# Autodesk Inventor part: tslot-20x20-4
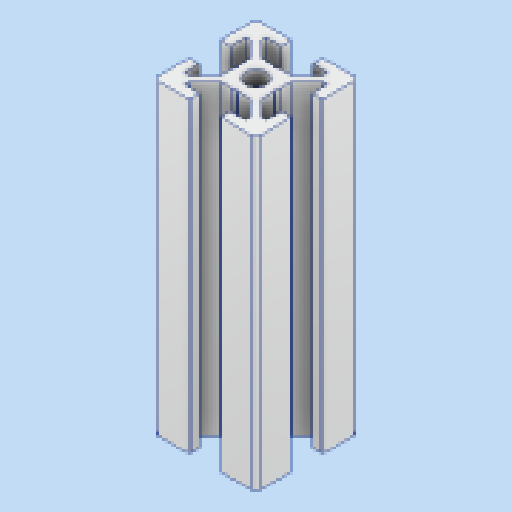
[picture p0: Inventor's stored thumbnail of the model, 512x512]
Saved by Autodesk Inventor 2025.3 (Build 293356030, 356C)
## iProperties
Created: 2025-03
Part Number: tslot-20x20-4
Material: Alluminio 6061
Document SubType Name: Modeling
Designer: Ryzen5700u
Density: 2.7 g/cm^3
Appearance: Alluminio - Piatto
Author: Ryzen5700u
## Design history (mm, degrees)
feature "Base1"
sketch "Schizzo1"
  geometry: L1 (3.761, -16)-(4.7, -16) reference; L2 (3.761, -16)-(0.7, -12.939) reference; L3 (0.7, -12.939)-(0.7, -10.52) reference; L4 (0.4, -10)-(0.7, -10.52) reference; L5 (0.4, -10)-(0.7, -9.48) reference; L6 (0.7, -7.061)-(0.7, -9.48) reference; L7 (3.761, -4)-(0.7, -7.061) reference; L8 (3.761, -4)-(4.7, -4) reference; L9 (4.7, -4)-(4.7, -7) reference; L10 (4.7, -7)-(6.4, -7) reference; L11 (6.7, -6.7)-(6.7, -1) reference; L12 (5.7, 0)-(0, 0) reference; L13 (-0.3, -2)-(-0.3, -0.3) reference; L14 (2.7, -2)-(-0.3, -2) reference; L15 (2.7, -2.939)-(2.7, -2) reference; L16 (2.7, -2.939)-(-0.361, -6) reference; L17 (-0.361, -6)-(-2.78, -6) reference; L18 (-3.3, -6.3)-(-2.78, -6) reference; L19 (-3.3, -6.3)-(-3.82, -6) reference; L20 (-6.239, -6)-(-3.82, -6) reference; L21 (-9.3, -2.939)-(-6.239, -6) reference; L22 (-9.3, -2.939)-(-9.3, -2) reference; L23 (-9.3, -2)-(-6.3, -2) reference; L24 (-6.3, -2)-(-6.3, -0.3) reference; L25 (-12.3, 0)-(-6.6, 0) reference; L26 (-13.3, -6.7)-(-13.3, -1) reference; L27 (-11.3, -7)-(-13, -7) reference; L28 (-11.3, -4)-(-11.3, -7) reference; L29 (-10.361, -4)-(-11.3, -4) reference; L30 (-10.361, -4)-(-7.3, -7.061) reference; L31 (-7.3, -7.061)-(-7.3, -9.48) reference; L32 (-7, -10)-(-7.3, -9.48) reference; L33 (-7, -10)-(-7.3, -10.52) reference; L34 (-7.3, -12.939)-(-7.3, -10.52) reference; L35 (-10.361, -16)-(-7.3, -12.939) reference; L36 (-10.361, -16)-(-11.3, -16) reference; L37 (-11.3, -16)-(-11.3, -13) reference; L38 (-11.3, -13)-(-13, -13) reference; L39 (-13.3, -13.3)-(-13.3, -19) reference; L40 (-12.3, -20)-(-6.6, -20) reference; L41 (-6.3, -18)-(-6.3, -19.7) reference; L42 (-9.3, -18)-(-6.3, -18) reference; L43 (-9.3, -17.061)-(-9.3, -18) reference; L44 (-9.3, -17.061)-(-6.239, -14) reference; L45 (-6.239, -14)-(-3.82, -14) reference; L46 (-3.3, -13.7)-(-3.82, -14) reference; L47 (-3.3, -13.7)-(-2.78, -14) reference; L48 (-0.361, -14)-(-2.78, -14) reference; L49 (2.7, -17.061)-(-0.361, -14) reference; L50 (2.7, -17.061)-(2.7, -18) reference; L51 (2.7, -18)-(-0.3, -18) reference; L52 (-0.3, -18)-(-0.3, -19.7) reference; L53 (5.7, -20)-(0, -20) reference; L54 (6.7, -13.3)-(6.7, -19) reference; L55 (4.7, -13)-(6.4, -13) reference; L56 (4.7, -16)-(4.7, -13) reference; C1 r 2.1 at (-3.3, -10) reference; A1 r 0.3 centre (6.4, -6.7) between (6.4, -7) and (6.7, -6.7) reference; A2 r 1 centre (5.7, -1) between (6.7, -1) and (5.7, 0) reference; A3 r 0.3 centre (0, -0.3) between (0, 0) and (-0.3, -0.3) reference; A4 r 0.3 centre (-6.6, -0.3) between (-6.3, -0.3) and (-6.6, 0) reference; A5 r 1 centre (-12.3, -1) between (-12.3, 0) and (-13.3, -1) reference; A6 r 0.3 centre (-13, -6.7) between (-13.3, -6.7) and (-13, -7) reference; A7 r 0.3 centre (-13, -13.3) between (-13, -13) and (-13.3, -13.3) reference; A8 r 1 centre (-12.3, -19) between (-13.3, -19) and (-12.3, -20) reference; A9 r 0.3 centre (-6.6, -19.7) between (-6.6, -20) and (-6.3, -19.7) reference; A10 r 0.3 centre (0, -19.7) between (-0.3, -19.7) and (0, -20) reference; A11 r 1 centre (5.7, -19) between (5.7, -20) and (6.7, -19) reference; A12 r 0.3 centre (6.4, -13.3) between (6.7, -13.3) and (6.4, -13) reference; 1 further point
extrude "Estrusione1" join sketch "Schizzo1" distance "d0" = 70; taper "d1" = 0 deg
node "Solido1"
node "Linea chiusa proiettata1"
